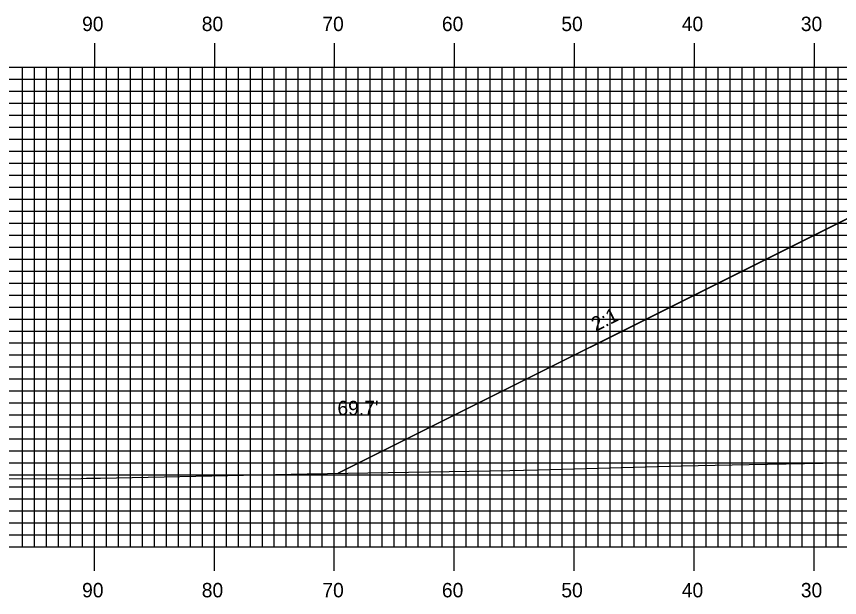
# Model space of a CAD drawing. Extents: x 1789730 to 1790074, y 442591 to 442811.
# Drawn here: x 1789799.7 to 1789868.3, y 442659.4 to 442707.9 of the extents above; entities that cross this region are included whole.
import ezdxf

# ---------------------------------------------------------------- set-up
doc = ezdxf.new("R2010")
doc.units = 0
for name, color, linetype in [('ANNOTATION', 7, 'Continuous'), ('D_Roadway_Centerline', 7, 'Continuous'), ('D_Roadway_SlopeLines', 7, 'Continuous'), ('D_Text_Standard', 7, 'Continuous'), ('H_V ANNOTATION', 7, 'Continuous'), ('MAJOR', 7, 'Continuous'), ('MINOR', 7, 'Continuous'), ('S_Roadway_Centerline', 7, 'Continuous')]:
    doc.layers.add(name, color=color, linetype=linetype)

msp = doc.modelspace()

# ---------------------------------------------------------------- linework, layer by layer
at = {"layer": 'D_Roadway_Centerline'}
msp.add_lwpolyline([(1789826.5, 442669.811), (1789868.433, 442690.777), (1789873.183, 442693.152), (1789876.183, 442693.272), (1789884.183, 442693.592), (1789896.183, 442693.832), (1789908.183, 442693.592), (1789916.183, 442693.272), (1789919.183, 442693.152), (1789923.933, 442690.777), (1789960.219, 442672.634)], dxfattribs=at)
at = {"layer": 'D_Roadway_SlopeLines'}
msp.add_lwpolyline([(1789873.183, 442693.152), (1789826.5, 442669.811)], dxfattribs=at)
at = {"layer": 'MAJOR'}
for p, q in [((1789806.183, 442705.669), (1789806.183, 442703.665)), ((1789816.183, 442705.669), (1789816.183, 442703.665)), ((1789826.183, 442705.669), (1789826.183, 442703.665)), ((1789836.183, 442705.669), (1789836.183, 442703.665)), ((1789846.183, 442705.669), (1789846.183, 442703.665)), ((1789856.183, 442705.669), (1789856.183, 442703.665)), ((1789866.183, 442705.669), (1789866.183, 442703.665)), ((1789756.183, 442703.665), (1790036.183, 442703.665)), ((1789756.183, 442703.665), (1790036.183, 442703.665)), ((1789806.183, 442663.665), (1789806.183, 442703.665)), ((1789816.183, 442663.665), (1789816.183, 442703.665)), ((1789826.183, 442663.665), (1789826.183, 442703.665)), ((1789836.183, 442663.665), (1789836.183, 442703.665)), ((1789846.183, 442663.665), (1789846.183, 442703.665)), ((1789856.183, 442663.665), (1789856.183, 442703.665)), ((1789866.183, 442663.665), (1789866.183, 442703.665)), ((1789756.183, 442698.665), (1790036.183, 442698.665)), ((1789756.183, 442693.665), (1790036.183, 442693.665)), ((1789756.183, 442688.665), (1790036.183, 442688.665)), ((1789756.183, 442683.665), (1790036.183, 442683.665)), ((1789756.183, 442678.665), (1790036.183, 442678.665)), ((1789756.183, 442673.665), (1790036.183, 442673.665)), ((1789756.183, 442668.665), (1790036.183, 442668.665)), ((1789756.183, 442663.665), (1790036.183, 442663.665)), ((1789756.183, 442663.665), (1790036.183, 442663.665)), ((1789806.183, 442661.661), (1789806.183, 442663.665)), ((1789816.183, 442661.661), (1789816.183, 442663.665)), ((1789826.183, 442661.661), (1789826.183, 442663.665)), ((1789836.183, 442661.661), (1789836.183, 442663.665)), ((1789846.183, 442661.661), (1789846.183, 442663.665)), ((1789856.183, 442661.661), (1789856.183, 442663.665)), ((1789866.183, 442661.661), (1789866.183, 442663.665))]:
    msp.add_line(p, q, dxfattribs=at)
at = {"layer": 'MINOR'}
for p, q in [((1789800.183, 442663.665), (1789800.183, 442703.665)), ((1789801.183, 442663.665), (1789801.183, 442703.665)), ((1789802.183, 442663.665), (1789802.183, 442703.665)), ((1789803.183, 442663.665), (1789803.183, 442703.665)), ((1789804.183, 442663.665), (1789804.183, 442703.665)), ((1789805.183, 442663.665), (1789805.183, 442703.665)), ((1789807.183, 442663.665), (1789807.183, 442703.665)), ((1789808.183, 442663.665), (1789808.183, 442703.665)), ((1789809.183, 442663.665), (1789809.183, 442703.665)), ((1789810.183, 442663.665), (1789810.183, 442703.665)), ((1789811.183, 442663.665), (1789811.183, 442703.665)), ((1789812.183, 442663.665), (1789812.183, 442703.665)), ((1789813.183, 442663.665), (1789813.183, 442703.665)), ((1789814.183, 442663.665), (1789814.183, 442703.665)), ((1789815.183, 442663.665), (1789815.183, 442703.665)), ((1789817.183, 442663.665), (1789817.183, 442703.665)), ((1789818.183, 442663.665), (1789818.183, 442703.665)), ((1789819.183, 442663.665), (1789819.183, 442703.665)), ((1789820.183, 442663.665), (1789820.183, 442703.665)), ((1789821.183, 442663.665), (1789821.183, 442703.665)), ((1789822.183, 442663.665), (1789822.183, 442703.665)), ((1789823.183, 442663.665), (1789823.183, 442703.665)), ((1789824.183, 442663.665), (1789824.183, 442703.665)), ((1789825.183, 442663.665), (1789825.183, 442703.665)), ((1789827.183, 442663.665), (1789827.183, 442703.665)), ((1789828.183, 442663.665), (1789828.183, 442703.665)), ((1789829.183, 442663.665), (1789829.183, 442703.665)), ((1789830.183, 442663.665), (1789830.183, 442703.665)), ((1789831.183, 442663.665), (1789831.183, 442703.665)), ((1789832.183, 442663.665), (1789832.183, 442703.665)), ((1789833.183, 442663.665), (1789833.183, 442703.665)), ((1789834.183, 442663.665), (1789834.183, 442703.665)), ((1789835.183, 442663.665), (1789835.183, 442703.665)), ((1789837.183, 442663.665), (1789837.183, 442703.665)), ((1789838.183, 442663.665), (1789838.183, 442703.665)), ((1789839.183, 442663.665), (1789839.183, 442703.665)), ((1789840.183, 442663.665), (1789840.183, 442703.665)), ((1789841.183, 442663.665), (1789841.183, 442703.665)), ((1789842.183, 442663.665), (1789842.183, 442703.665)), ((1789843.183, 442663.665), (1789843.183, 442703.665)), ((1789844.183, 442663.665), (1789844.183, 442703.665)), ((1789845.183, 442663.665), (1789845.183, 442703.665)), ((1789847.183, 442663.665), (1789847.183, 442703.665)), ((1789848.183, 442663.665), (1789848.183, 442703.665)), ((1789849.183, 442663.665), (1789849.183, 442703.665)), ((1789850.183, 442663.665), (1789850.183, 442703.665)), ((1789851.183, 442663.665), (1789851.183, 442703.665)), ((1789852.183, 442663.665), (1789852.183, 442703.665)), ((1789853.183, 442663.665), (1789853.183, 442703.665)), ((1789854.183, 442663.665), (1789854.183, 442703.665)), ((1789855.183, 442663.665), (1789855.183, 442703.665)), ((1789857.183, 442663.665), (1789857.183, 442703.665)), ((1789858.183, 442663.665), (1789858.183, 442703.665)), ((1789859.183, 442663.665), (1789859.183, 442703.665)), ((1789860.183, 442663.665), (1789860.183, 442703.665)), ((1789861.183, 442663.665), (1789861.183, 442703.665)), ((1789862.183, 442663.665), (1789862.183, 442703.665)), ((1789863.183, 442663.665), (1789863.183, 442703.665)), ((1789864.183, 442663.665), (1789864.183, 442703.665)), ((1789865.183, 442663.665), (1789865.183, 442703.665)), ((1789867.183, 442663.665), (1789867.183, 442703.665)), ((1789868.183, 442663.665), (1789868.183, 442703.665)), ((1789756.183, 442702.665), (1790036.183, 442702.665)), ((1789756.183, 442701.665), (1790036.183, 442701.665)), ((1789756.183, 442700.665), (1790036.183, 442700.665)), ((1789756.183, 442699.665), (1790036.183, 442699.665)), ((1789756.183, 442697.665), (1790036.183, 442697.665)), ((1789756.183, 442696.665), (1790036.183, 442696.665)), ((1789756.183, 442695.665), (1790036.183, 442695.665)), ((1789756.183, 442694.665), (1790036.183, 442694.665)), ((1789756.183, 442692.665), (1790036.183, 442692.665)), ((1789756.183, 442691.665), (1790036.183, 442691.665)), ((1789756.183, 442690.665), (1790036.183, 442690.665)), ((1789756.183, 442689.665), (1790036.183, 442689.665)), ((1789756.183, 442687.665), (1790036.183, 442687.665)), ((1789756.183, 442686.665), (1790036.183, 442686.665)), ((1789756.183, 442685.665), (1790036.183, 442685.665)), ((1789756.183, 442684.665), (1790036.183, 442684.665)), ((1789756.183, 442682.665), (1790036.183, 442682.665)), ((1789756.183, 442681.665), (1790036.183, 442681.665)), ((1789756.183, 442680.665), (1790036.183, 442680.665)), ((1789756.183, 442679.665), (1790036.183, 442679.665)), ((1789756.183, 442677.665), (1790036.183, 442677.665)), ((1789756.183, 442676.665), (1790036.183, 442676.665)), ((1789756.183, 442675.665), (1790036.183, 442675.665)), ((1789756.183, 442674.665), (1790036.183, 442674.665)), ((1789756.183, 442672.665), (1790036.183, 442672.665)), ((1789756.183, 442671.665), (1790036.183, 442671.665)), ((1789756.183, 442670.665), (1790036.183, 442670.665)), ((1789756.183, 442669.665), (1790036.183, 442669.665)), ((1789756.183, 442667.665), (1790036.183, 442667.665)), ((1789756.183, 442666.665), (1790036.183, 442666.665)), ((1789756.183, 442665.665), (1790036.183, 442665.665)), ((1789756.183, 442664.665), (1790036.183, 442664.665))]:
    msp.add_line(p, q, dxfattribs=at)
at = {"layer": 'S_Roadway_Centerline'}
msp.add_lwpolyline([(1789756.183, 442669.243), (1789769.529, 442669.398), (1789769.816, 442669.4), (1789773.123, 442669.062), (1789782.366, 442669.278), (1789790.201, 442669.353), (1789805.087, 442669.369), (1789805.525, 442669.385), (1789806.681, 442669.4), (1789823.907, 442669.768), (1789840.827, 442670.05), (1789841.954, 442670.073), (1789843.126, 442670.101), (1789855.11, 442670.417), (1789860.761, 442670.53), (1789876.169, 442670.814)], dxfattribs=at)

# ---------------------------------------------------------------- texts
at = {"layer": 'ANNOTATION'}
msp.add_text('2:1', height=1.2, rotation=26.56505, dxfattribs=at).set_placement((1789847.987, 442681.591))
at = {"layer": 'D_Text_Standard'}
msp.add_text("69.7'", height=1.2, dxfattribs=at).set_placement((1789826.444, 442674.645))
at = {"layer": 'H_V ANNOTATION'}
for s, p in [('90', (1789805.155, 442706.665)), ('80', (1789815.133, 442706.665)), ('70', (1789825.187, 442706.665)), ('60', (1789835.155, 442706.665)), ('50', (1789845.112, 442706.665)), ('40', (1789855.155, 442706.665)), ('30', (1789865.08, 442706.665)), ('90', (1789805.155, 442659.465)), ('80', (1789815.133, 442659.465)), ('70', (1789825.187, 442659.465)), ('60', (1789835.155, 442659.465)), ('50', (1789845.112, 442659.465)), ('40', (1789855.155, 442659.465)), ('30', (1789865.08, 442659.465))]:
    msp.add_text(s, height=1.2, dxfattribs=at).set_placement(p)

doc.saveas('drawing.dxf')
